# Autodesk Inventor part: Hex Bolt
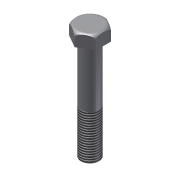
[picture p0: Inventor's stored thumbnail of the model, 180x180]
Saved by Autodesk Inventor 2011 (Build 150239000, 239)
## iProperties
Created: 2010-03
Part Number: Hex Bolt
Document SubType Name: Modeling
Designer: bhakira
Density: 1 g/cm^3
Author: bhakira
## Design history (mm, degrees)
sketch "Sketch1"
  geometry: C1 r 10 at (0, 0)
  constraints: 1 centre point
  dimensions: "d1" = 20 diameter of C1
extrude "Extrusion1" new body sketch "Sketch1" distance "d2" = 115; taper "d3" = 0 deg
sketch "Sketch2"
  geometry: L1 (0, 17.321)-(15, 8.66); L2 (15, 8.66)-(15, -8.66); L3 (15, -8.66)-(0, -17.321); L4 (0, -17.321)-(-15, -8.66); L5 (-15, -8.66)-(-15, 8.66); L6 (-15, 8.66)-(0, 17.321); 1 further point
  constraints: 12 end point, 13 other
  dimensions: "d4" = 30 distance between parallel lines of L2 L5
extrude "Extrusion2" join sketch "Sketch2" distance "d5" = 15; taper "d6" = 0 deg
sketch "Sketch3"
  geometry: L1 (10.19, 129.3)-(12.321, 129.3); L2 (17.321, 124.3)-(17.321, 122.815); L3 (0, -26.067)-(0, 156.403) reference; A1 r 5 centre (12.321, 124.3) between (17.321, 124.3) and (12.321, 129.3); 1 further point
  constraints: 4 end point, 2 point on circle, 2 tangent, 1 centre point
  dimensions: "d7" = 5 radius of A1
revolve "Revolution1" sketch "Sketch3" stored, may be unused: angle "d9" = 90 deg
thread "Thread1" dims "d10" = 50, "d11" = 0
body "Solid1"
other parameters: "d8" = 90 deg
